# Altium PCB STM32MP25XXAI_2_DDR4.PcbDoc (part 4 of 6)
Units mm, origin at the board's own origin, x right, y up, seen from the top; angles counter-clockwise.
Board outline 172 x 137 mm, 4 copper layers (Top Layer, Signal Layer 1, Signal Layer 2, Bottom Layer), stack 1.614 mm thick; 241 components, 153 nets, 1312 pads, 924 vias.
Unrouted connection lines stored in the file: 13.
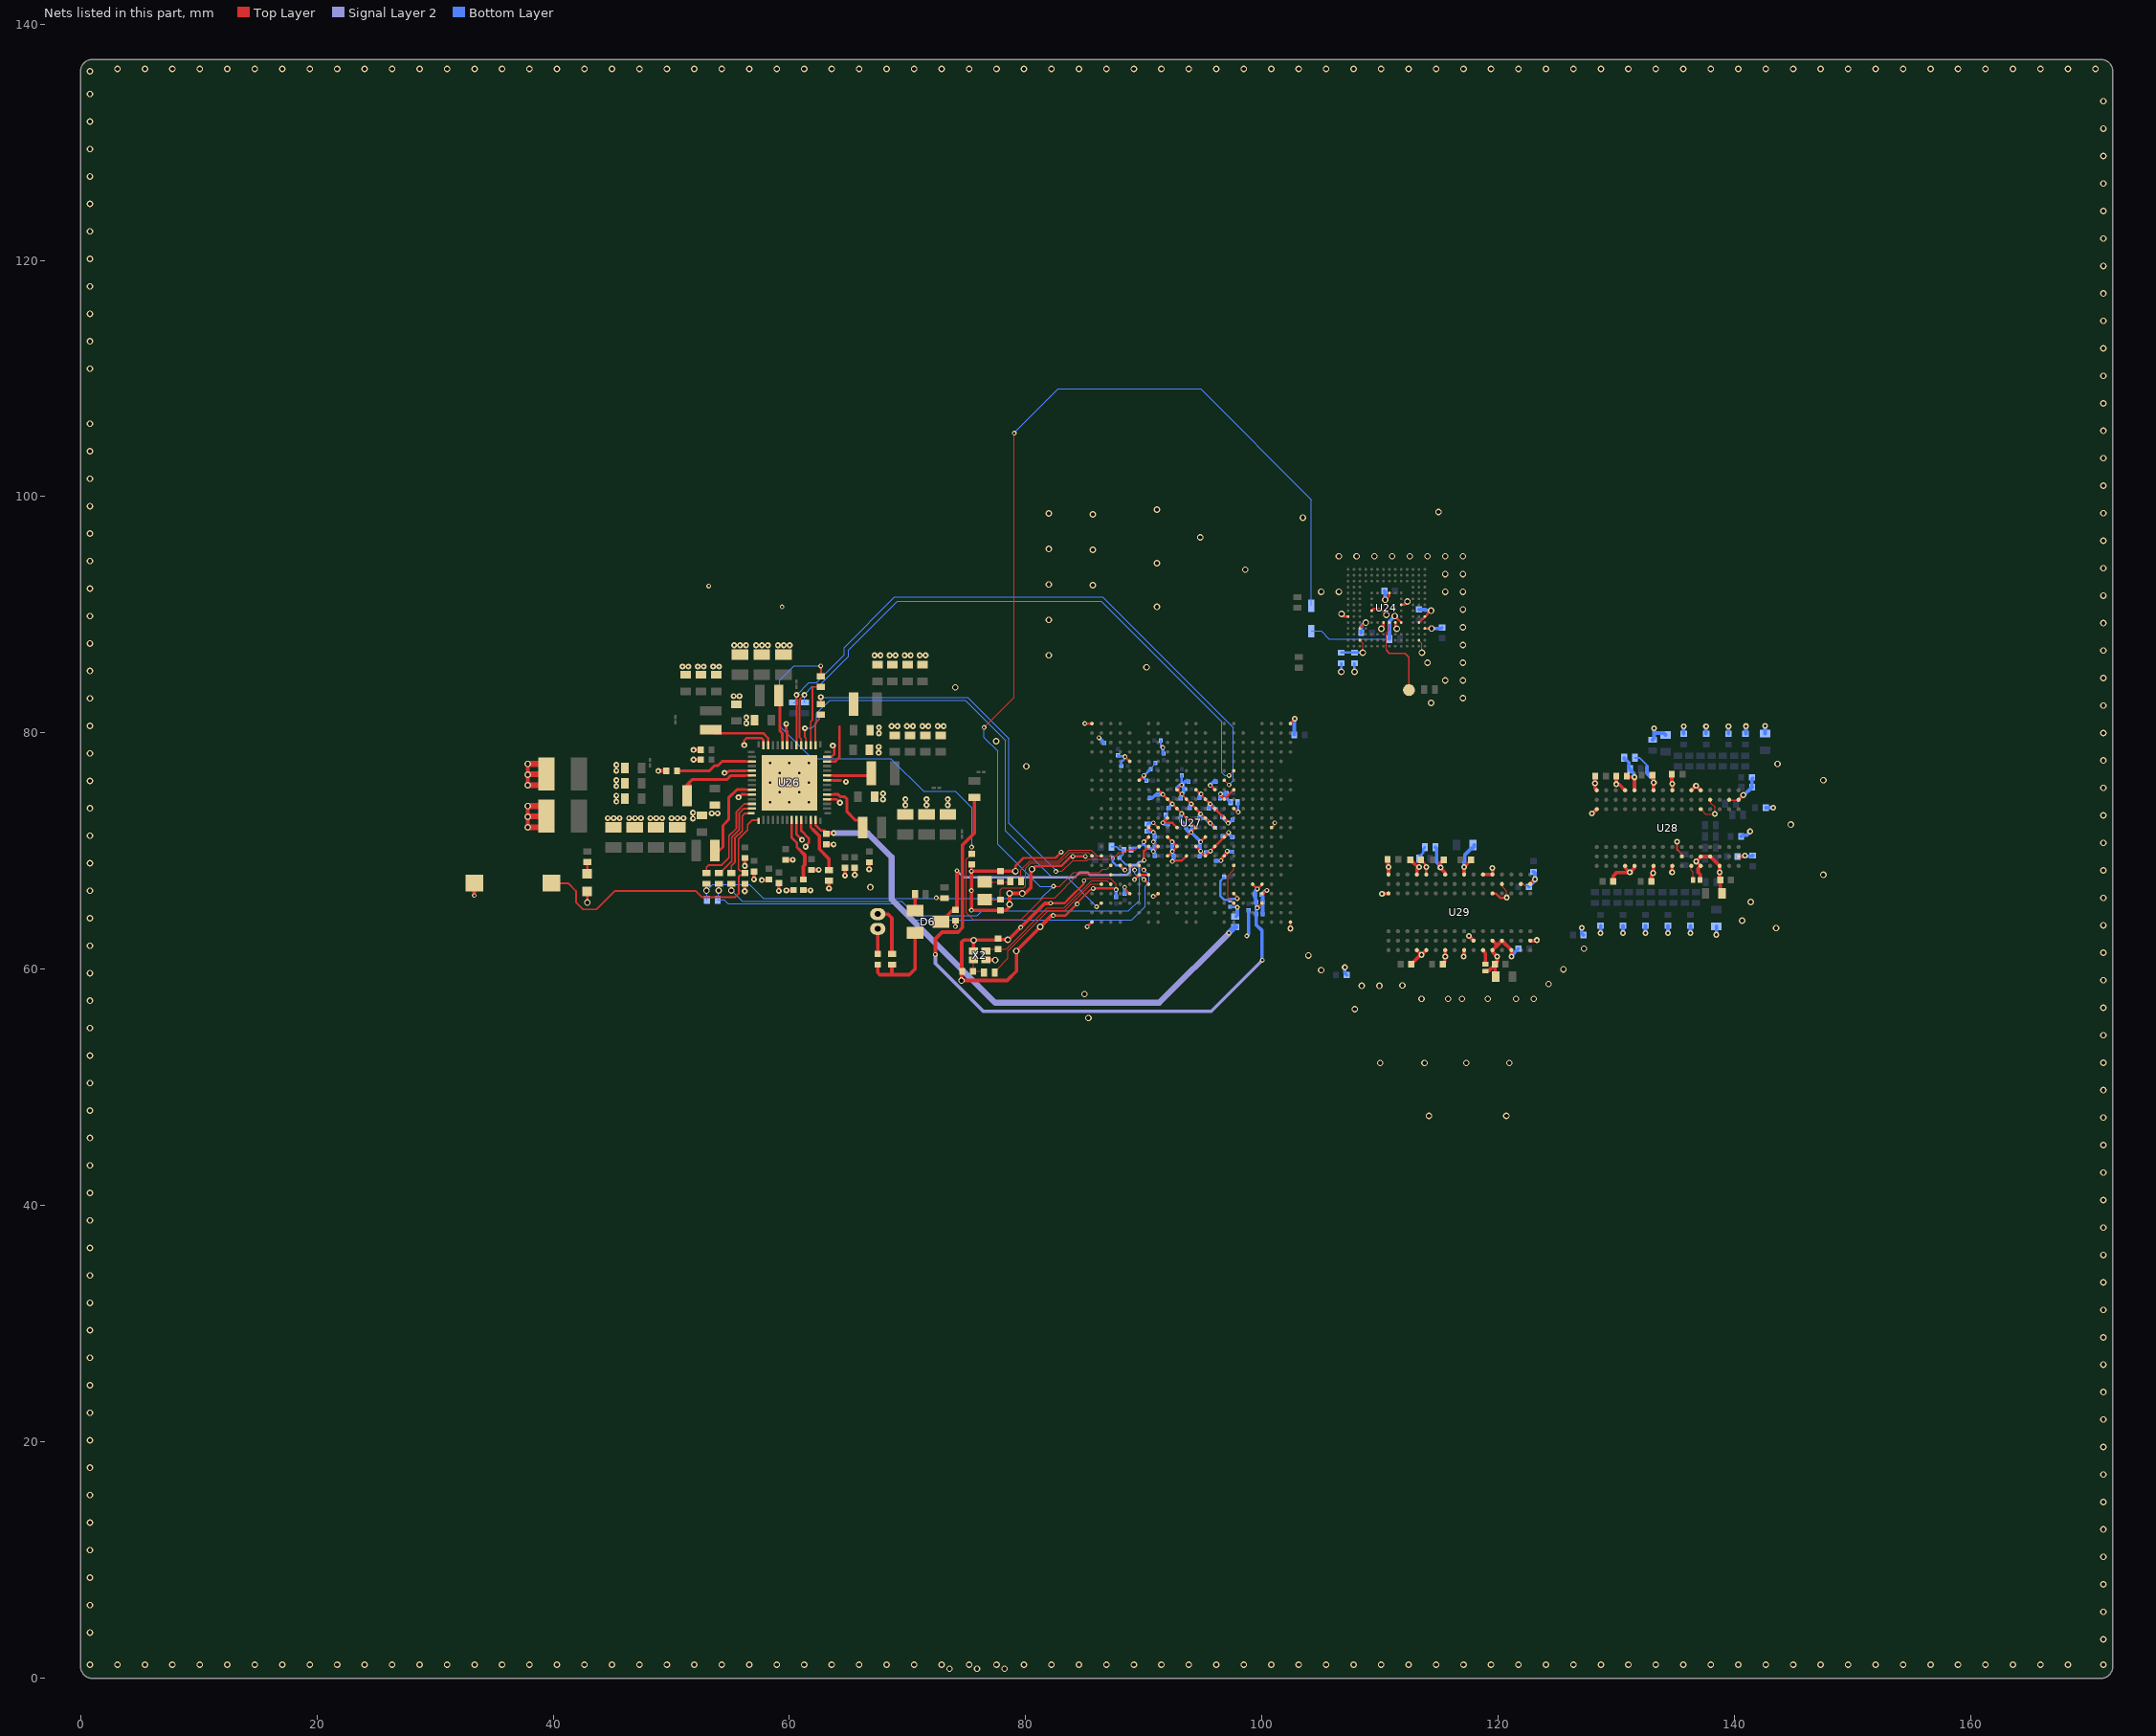
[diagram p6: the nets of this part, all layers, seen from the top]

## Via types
v1: diameter 0.55, hole 0.35, Top Layer to Bottom Layer, 432 vias
v2: diameter 0.4, hole 0.2, Top Layer to Bottom Layer, tented both sides, 202 vias
v3: diameter 0.5, hole 0.2, Top Layer to Bottom Layer, 146 vias
v4: diameter 0.5, hole 0.25, Top Layer to Bottom Layer, 144 vias

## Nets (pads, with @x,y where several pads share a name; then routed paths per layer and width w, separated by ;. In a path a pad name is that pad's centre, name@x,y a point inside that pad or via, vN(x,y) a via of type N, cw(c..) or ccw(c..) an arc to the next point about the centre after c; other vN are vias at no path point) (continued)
GND: B2.1 C1.2 C2.1 C3.1 C4.2 C5.1 C6.1 C7.1 C8.1 C9.1 C10.1 C11.2 C12.1 C13.2 C14.1 C15.1 C16.2 C17.1 C18.2 C19.1 C20.1 C21.1 C22.1 C23.1 C24.1 C25.1 C26.1 C27.1 C28.1 C29.1 C30.1 C31.1 C32.1 C33.1 C34.1 C35.1 C36.1 C37.1 C38.1 C39.1 C40.1 C41.1 C42.2 C43.1 C44.2 C45.1 C46.1 C47.2 C48.1 C49.1 C50.1 C51.1 C52.1 C53.1 C54.2 C55.1 C56.1 C57.1 C58.1 C59.1 C60.1 C61.1 C62.1 C63.1 C64.1 C65.1 C66.1 C67.1 C68.1 C69.1 C70.1 C71.1 C72.1 C73.1 C74.1 C75.1 C76.1 C77.1 C78.1 C79.1 C80.1 C81.2 C82.1 C83.1 C84.1 C85.1 C86.2 C87.1 C89.1 C90.1 C91.2 C92.2 C93.1 C94.1 C95.1 C96.1 C97.1 C98.1 C99.1 C141.2 C142.2 C152.1 C153.1 C154.1 C155.1 C156.1 C157.1 C177.1 C178.1 C179.1 C180.1 C181.1 C182.1 C183.1 C184.1 C186.1 C187.1 C188.1 C189.1 C190.2 C193.1 C199.1 C200.1 C202.1 C204.1 C206.1 C207.1 C208.2 C209.1 C211.1 C212.1 C217.2 C226.1 C234.1 C236.1 C238.1 C239.1 C245.1 C247.1 C254.1 C255.1 C256.1 C257.1 C258.1 C259.1 C261.1 C262.1 C264.1 C275.1 C276.1 C277.1 C278.1 C279.1 C280.1 C281.1 C282.1 C283.1 C284.1 C285.1 LD11.2 R57.1 R63.1 R73.1 R252.1 R262.1 R301.1 R303.1 U24.A6 U24.C4 U24.E7 U24.G5 U24.H10 U24.J5 U24.K8 U24.N2 U24.N5 U24.P4 U24.P6 U26.9 U26.10 U26.18 U26.22 U26.27 U26.36 U26.41 U26.47 U26.52 U26.57 U27.A1 U27.A22 U27.AB1 U27.AB22 U27.E5 U27.G6 U27.H8 U27.H10 U27.H12 U27.H14 U27.H16 U27.J9 U27.J11 U27.J13 U27.J15 U27.K10 U27.K12 U27.K14 U27.L9 U27.L11 U27.L13 U27.L15 U27.M7 U27.M10 U27.M12 U27.M14 U27.M20 U27.N7 U27.N9 U27.N11 U27.N13 U27.N15 U27.P8 U27.P10 U27.P12 U27.P14 U27.R9 U27.R11 U27.R13 U27.R15 U27.T4 U27.U6 U27.U7 U27.W5 U27.W8 U27.W16 U27.W19 U28.A2 U28.A8 U28.B2 U28.C9 U28.D2 U28.D8 U28.E1 U28.E3 U28.E8 U28.E9 U28.F1 U28.G8 U28.H1 U28.H9 U28.K1 U28.K9 U28.M9 U28.N1 U28.N9 U28.T1 U28.T3 U29.A2 U29.A8 U29.B2 U29.C9 U29.D2 U29.D8 U29.E1 U29.E3 U29.E8 U29.E9 U29.F1 U29.G8 U29.H1 U29.H9 U29.K1 U29.K9 U29.M9 U29.N1 U29.N9 U29.T1 U29.T3 X2.2 X2.4 | length 281.4
  Top Layer w0.09: v2(84.925,67.5) 85.12,67.695 87.155,67.695 87.183,67.667 87.65,67.2 v2(87.65,66.75) ; U24.N2@113.275,87.85 113.525,87.6 v1(113.525,86.8) ; U28.F1@136.307,75.146 U28.F1@136.326,75.127
  Top Layer w0.1: v3@44.624,72.799 v3@44.625,72.8 ; X2.2@75.547,61.575 X2.2@75.548,61.576 ; v1@75.573,62.448 v1(75.587,62.462) v1@75.6,62.475 ; v4@110.15,66.435 v4@110.155,66.43 ; v4@110.155,66.402 v4@110.155,66.43 ; v4@110.163,66.422 v4@110.155,66.43 ; U29.D2@120.3,67.225 120.343,67.183 120.343,66.972 120.7,66.615 v4(120.7,66.08) ; U29.B2@121.9,67.225 122.122,67.225 122.232,67.115 122.59,67.115 U29.A2@122.7,67.225 122.825,67.35 ; U28.E3@137.125,73.525 137.158,73.525 137.533,73.15 138.31,73.15 138.332,73.128 138.332,73.718 137.975,74.075 137.975,74.285 U28.D2@137.932,74.328
  Top Layer w0.15: v2(84.345,65.531) 84.345,65.598 84.448,65.702 84.448,65.708 85.465,66.725 85.523,66.725 85.636,66.838 v2(85.703,66.838) ; v4(135.125,70.8) 135.125,70.125 135.525,69.725 U28.G8@135.525,69.55 ; U28.B2@139.525,74.35 139.566,74.31 140.285,74.31 U28.A2@140.325,74.35
  Top Layer w0.2: v1(42.887,65.648) LD11.2@42.887,66.577 ; U26.27@63.17,78 63.579,78 63.77,78.191 63.77,78.91 v3@63.816,78.956 ; v3(63.67,78.93) v3@63.727,78.873 ; C87.1@74.05,64.125 74.05,63.634 v2(74.051,63.633) ; v2(75.402,68.305) 75.416,68.319 C33.1@75.416,68.915 ; v1(79.125,68.3) 79.125,68.75 79.8,69.425 82.507,69.425 v2(83.002,69.92) ; v1(80.525,68.475) 80.568,68.475 80.818,68.725 81.262,68.725 81.287,68.75 83.012,68.75 83.784,69.522 83.94,69.522 v2(83.978,69.56) v2(85.046,69.56) ; v2(82.1,65.6) 83.28,65.6 83.703,66.023 84.887,67.207 84.887,67.462 v2(84.925,67.5) ; v2(82.325,64.55) 83.364,64.55 v2(84.345,65.531) ; v2(85,80.805) 85.005,80.8 U27.A1@85.6,80.8 ; v2(85.2,63.6) U27.AB1@85.6,64 ; v2(85.703,66.838) 87.508,66.838 87.596,66.75 v2(87.65,66.75) ; U27.T4@88,68.8 v2(88.4,68.4) ; v2(88.37,66.944) 88.408,66.905 88.408,66.792 U27.W5@88.8,66.4 ; v2(88.4,78) U27.E5@88.8,77.6 ; v2(89.2,67.6) U27.U6@89.6,68 U27.U7@90.4,68 ; U27.G6@89.6,76 v2(90,76.4) ; v2(90,70.8) U27.N7@90.4,71.2 ; v2(90.788,66.173) 90.827,66.211 90.984,66.211 91.173,66.4 U27.W8@91.2,66.4 ; v2@90.8,70 U27.P8@91.2,70.4 v2(90.8,70.8) ; U27.H8@91.2,75.2 v2(91.6,74.8) U27.J9@92,74.4 v2(92.4,74) v2@93.225,73.175 ; U27.R9@92,69.6 92.025,69.6 v2(92.4,69.975) 92.8,70.375 U27.P10@92.8,70.4 92.4,70.8 U27.N9@92,71.2 ; U27.L9@92,72.8 v2(91.6,72.4) 92.4,72.4 U27.M10@92.8,72 ; v2@92.454,69.1 92.4,69.1 92.5,69.2 93.2,69.2 U27.R11@93.6,69.6 ; v2(93.2,73.175) v2@93.225,73.175 ; v2(93.201,75.6) 92.801,75.2 v2@93.226,74.775 ; v2(93.226,74.85) v2@93.226,74.775 ; U27.N11@93.6,71.2 v2(94,71.6) U27.M12@94.4,72 v2@93.225,73.175 ; U27.P12@94.4,70.4 v2(94.8,70) U27.R13@95.2,69.6 95.787,70.188 ; U27.H12@94.407,75.2 94.757,74.85 v2(94.832,74.85) 94.832,74.775 v2(95.607,74) U27.L15@96.807,72.8 ; v2(94.8,70.8) U27.N13@95.2,71.2 ; v2@95.625,75.575 U27.H14@96,75.2 ; U27.P14@96,70.4 95.787,70.188 ; U27.M14@96,72 95.626,72.375 94.851,73.15 v2(94.801,73.15) 94.801,73.2 v2(94.001,74) v2@93.226,74.775 ; v2(96.475,74.85) 96.514,74.812 96.514,74.686 U27.J15@96.8,74.4 U27.H16@97.6,75.2 ; U27.L15@96.8,72.8 97.087,72.513 97.087,72.413 v2(97.125,72.375) ; v2(97.175,71.575) 95.787,70.188 ; U27.W16@97.6,66.4 97.862,66.138 97.862,66.038 v2(97.9,66) ; U27.W19@100,66.4 100.019,66.419 100.144,66.419 v2(100.4,66.675) ; U27.M20@100.825,72 U27.M20@100.8,72 101.018,72.218 101.018,72.343 v2(101.075,72.4) v2@101.075,72.329 ; v4(102.4,63.45) U27.AB22@102.4,64 ; U27.A22@102.4,80.8 102.4,80.811 102.75,81.161 v4@102.75,81.175 ; v1(106.725,90.075) 106.95,89.85 U24.A6@107.275,89.85 ; U24.C4@108.275,88.85 108.725,89.3 108.735,89.3 v1(108.775,89.34) ; U24.E7@109.275,90.35 109.426,90.501 110.011,90.501 110.516,89.995 v1(110.525,89.995) ; v1(110.1,88.825) 110.1,88.913 110.275,89.088 U24.G5@110.275,89.35 ; v1(110.425,91.275) 110.775,91.625 U24.H10@110.775,91.85 ; U24.J5@111.275,89.35 111.275,89.045 111.4,88.92 v1(111.4,88.825) ; U24.K8@111.775,90.85 112.025,90.85 v1(112.3,91.125) ; U24.N5@113.275,89.35 U24.P6@113.775,89.85 114.275,90.35 v1(114.3,90.35) ; U24.P4@113.775,88.85 v1(114.35,88.85) ; U29.E3@119.5,66.425 119.503,66.422 119.769,66.422 120.142,66.05 120.67,66.05 v4(120.7,66.08) ; v4@120.687,66.012 v4@120.7,66.025
  Top Layer w0.21: v3(56.175,78.975) 56.175,79.375 56.38,79.58 57.609,79.58 57.8,79.389 U26.41@57.8,78.97 ; 56.275,74.8 U26.52@56.83,74.8 ; 56.275,76.8 U26.47@56.83,76.8 ; U26.36@59.8,78.97 59.8,79.525 ; U26.9@60.6,72.63 60.6,71.42 v3(61.068,70.952) ; U26.10@61,72.63 61,71.734 61.635,71.099 61.635,70.72 61.37,70.456 v3(61.37,70.377) ; U26.18@63.17,74.4 63.972,74.4 v3(64.272,74.1) ; U26.22@63.17,76 63.725,76
  Top Layer w0.25: v3(54.508,76.625) 54.556,76.673 54.757,76.673 54.884,76.8 56.275,76.8 ; v3(55.687,74.563) 55.721,74.563 55.959,74.8 56.275,74.8 ; v3(59.725,80.775) 59.725,80.214 59.8,80.139 59.8,79.525 ; 63.725,76 64.33,76 ; v3@64.257,74.1 v3(64.272,74.1)
  Top Layer w0.3: v2(33.319,66.245) 33.324,66.25 33.324,67.279 B2.1@33.34,67.295 ; v1(37.848,72.014) v1(37.848,72.914) v1(37.848,73.814) ; v1(37.848,75.576) v1(37.848,76.476) v1(37.848,77.376) ; v3(48.895,76.79) C43.1@49.555,76.79 ; v3(51.885,77.75) C40.1@52.495,77.75 ; v3(51.885,78.575) C39.1@52.495,78.575 ; v3@56.225,68.81 C217.2@56.225,69.42 ; v3@56.227,66.58 C155.1@56.227,67.185 ; v3(57,67.61) C154.1@57,68.215 ; v3(57.665,67.55) C142.2@58.275,67.55 ; v3@59.1,66.69 C141.2@59.1,67.3 ; C153.1@59.675,69.27 v3(60.285,69.27) ; v3(59.74,66.68) C91.2@60.35,66.68 ; C208.2@61.175,66.68 v3(61.785,66.68) ; C209.1@61.85,68.42 v3(62.485,68.42) ; C156.1@63.125,70.57 v3(63.735,70.57) ; v3(63.35,66.84) R57.1@63.35,67.5 ; v3(64.7,67.93) C189.1@64.7,68.59 ; v3(65.525,67.99) C188.1@65.525,68.59 C188.1@65.525,68.65 ; v3@66.75,68.465 66.747,68.467 66.747,69.063 C190.2@66.75,69.065 ; C92.2@74.563,59.875 74.563,59.087 74.588,59.063 78.438,59.063 79.225,59.85 79.225,61.525 v1(79.2,61.55) 81.225,63.575 v1(81.225,63.6) 82.156,64.531 82.306,64.531 v2(82.325,64.55) ; C92.2@74.625,59.825 74.576,59.874 74.576,62.299 74.752,62.475 75.6,62.475 76,62.475 76.013,62.488 76.663,62.488 76.675,62.475 77.5,62.475 77.625,62.6 C90.1@77.65,62.6 77.736,62.514 v1@78.475,62.514 ; v2(75.4,65) C86.2@77.85,65 ; 75.4,65.275 v2@75.4,66.65 ; v2@75.4,68.3 v2@75.402,68.3 ; v2(75.402,66.655) v2@75.402,68.3 ; v2(75.402,68.305) v2@75.402,68.3 ; X2.2@75.573,61.551 v1@75.573,62.448 ; X2.4@76.66,60.788 76.667,60.794 77.408,60.794 v1(77.415,60.788) ; C86.2@77.955,65.105 C86.2@77.85,65 ; v1(78.475,62.5) 78.525,62.5 v2(79.575,63.55) 81.606,65.581 v2@82.081,65.581 ; v1(79.125,68.3) C81.2@77.85,68.3 v2@75.402,68.3 ; v1(80.525,68.475) 80.43,68.38 80.43,66.905 79.993,66.468 79.748,66.468 v1(79.7,66.42) 79.695,66.425 v1(78.625,66.425) v1(78.625,65.5) 78.578,65.452 78.578,65.239 78.339,65 C86.2@77.85,65 ; U27.M7@90.4,72 v2(90.8,71.6) ; v2(96.525,69.2) 96.544,69.219 96.544,69.344 U27.R15@96.8,69.6 96.975,69.775 96.975,69.898 97.05,69.973 v2(97.05,70) ; v4@110.155,66.402 110.166,66.413 110.688,66.413 U29.T3@110.7,66.425 ; C77.1@110.625,69.3 110.663,69.263 110.663,68.688 v4(110.7,68.65) U29.T1@110.7,68.025 ; C78.1@112.55,69.275 112.55,69.25 112.655,69.145 112.68,69.145 113.143,68.682 113.198,68.682 113.236,68.644 113.236,68.59 113.136,68.49 113.136,68.452 113.1,68.416 U29.N1@113.1,68.025 ; C95.1@112.625,60.425 113.425,61.225 v4(113.5,61.225) ; U29.N9@113.1,61.625 v4(113.5,61.225) ; U29.M9@113.9,61.625 v4(113.5,61.225) ; C94.1@115.294,60.422 115.294,60.447 115.462,60.615 115.462,61.037 v4(115.5,61.075) U29.K9@115.5,61.625 ; C76.1@115.375,69.275 115.375,69.25 115.27,69.145 115.246,69.145 115.071,68.969 115.071,68.621 115.05,68.6 115.491,68.159 115.491,68.035 U29.K1@115.5,68.025 ; v4(117.05,61.075) 117.1,61.125 U29.H9@117.1,61.625 ; U29.H1@117.1,68.025 v4(117.1,68.65) ; v4(117.1,68.65) 117.57,69.12 117.57,69.17 C80.1@117.675,69.275 ; v4(117.5,62.825) U29.G8@117.9,62.425 ; U29.F1@118.7,68.025 U29.E1@119.5,68.025 v4(119.5,68.575) ; R73.1@118.9,59.85 118.95,59.9 119.208,59.9 119.595,60.287 119.595,60.295 119.709,60.409 119.717,60.409 119.717,59.458 C99.1@119.775,59.4 ; U29.E8@119.5,62.425 119.836,62.089 119.836,62.067 119.894,62.009 ; U29.E9@119.51,61.625 119.894,62.009 ; U29.E9@119.52,61.606 119.52,61.456 v4(119.9,61.075) 119.9,60.65 C93.1@119.688,60.438 ; 119.894,62.015 119.894,62.009 ; U29.D8@120.3,62.415 119.894,62.009 ; U29.D8@120.3,62.425 U29.C9@121.1,61.625 v4(121.1,61.075) ; U29.A8@122.7,62.425 v4@123.2,62.425 ; 122.825,67.35 v4(123.1,67.625) ; v4@127.855,73.231 127.935,73.231 127.942,73.238 128.014,73.238 U28.T3@128.325,73.55 ; C51.1@128.195,76.371 128.185,76.361 128.185,75.76 v4(128.175,75.75) 128.175,75.314 128.325,75.164 U28.T1@128.325,75.15 ; C83.1@129.725,67.45 129.725,67.903 130.022,68.2 v4(131.125,68.2) ; v4(129.965,75.675) 130.003,75.637 130.239,75.637 U28.N1@130.716,75.16 ; v4@129.97,75.68 129.97,76.345 C49.1@129.975,76.35 ; U28.N9@130.725,68.75 130.725,68.6 v4(131.125,68.2) ; U28.M9@131.525,68.75 131.525,68.6 v4(131.125,68.2) ; C84.1@132.95,67.45 132.95,67.893 133,67.943 133,68.05 v4(133.1,68.15) 133.125,68.175 U28.K9@133.125,68.75 ; C50.1@133.025,76.425 133.112,76.338 133.112,75.838 v4(133.15,75.8) 133.125,75.775 U28.K1@133.125,75.15 ; C48.1@134.675,76.375 134.675,75.75 v4(134.725,75.7) U28.H1@134.725,75.15 ; v4(134.7,68.2) 134.7,68.725 U28.H9@134.725,68.75 ; U28.F1@136.325,75.15 v4(136.725,75.55) U28.E1@137.132,75.143 ; R63.1@137.075,67.55 137.075,68.025 136.9,68.2 136.9,68.525 U28.E9@137.125,68.75 v4(136.75,69.125) 137.125,69.5 U28.E8@137.125,69.55 U28.D8@137.925,69.55 U28.C9@138.725,68.75 v4(138.725,68.2) 138.725,67.6 C82.1@138.775,67.55 138.793,67.533 138.793,66.558 C85.1@138.925,66.425 ; U28.A8@140.325,69.55 140.325,69.526 140.631,69.526 140.729,69.623 140.874,69.623 v4(140.875,69.625) ; U28.A2@140.325,74.35 v4(140.725,74.75)
  Top Layer w0.5: v1(37.848,72.014) 39.39,72.014 C18.2@39.437,72.061 ; v1(37.848,72.914) 37.862,72.914 37.909,72.961 C18.2@39.437,72.961 ; v1(37.848,73.814) C18.2@39.379,73.814 ; v1(37.848,75.576) 39.39,75.576 C42.2@39.437,75.623 ; v1(37.848,76.476) 37.862,76.476 37.909,76.523 C42.2@39.437,76.523 ; v1(37.848,77.376) C42.2@39.379,77.376
  Bottom Layer w0.1: C73.1@90.575,76.925 90.7,77.05 90.7,77.13 90.85,77.28 90.85,77.35 C66.1@90.9,77.4 ; C212.1@91.86,73.1 92.032,73.272 92.032,73.582 C3.1@92.1,73.65 ; C10.1@92.35,70.327 C10.1@92.35,70.45 ; 132.555,77.141 132.555,77.262
  Bottom Layer w0.15: R303.1@131.55,77.9 131.952,77.9 132.639,77.213 132.639,76.517
  Bottom Layer w0.2: C75.1@87.375,69.425 87.375,69.075 87.65,68.8 87.9,68.8 88.3,68.4 v2(88.4,68.4) ; C70.1@87.8,78.1 87.862,78.038 88.362,78.038 v2(88.4,78) 88.405,77.996 88.405,77.854 88.205,77.655 88.18,77.655 88.163,77.655 88.075,77.567 C275.1@88.075,77.2 ; C79.1@88.9,70.125 89.075,70.3 89.625,70.3 89.962,70.636 89.962,70.761 v2(90,70.8) 90.038,70.761 90.038,70.522 C234.1@90.275,70.285 ; v2@89.988,76.388 90.038,76.338 90.038,76.137 C69.1@90.205,75.97 ; v2(90,76.4) 90.525,76.925 C73.1@90.575,76.925 ; C66.1@90.9,77.4 C66.1@90.975,77.475 ; C97.1@91.425,79.375 91.425,78.955 91.6,78.781 v2(91.6,78.775) ; v2(93.201,75.6) C71.1@93.201,76.4 ; C11.2@95.25,69.9 95.312,69.962 95.587,69.962 v2(95.625,70) ; C89.1@96.75,67.8 96.75,67.75 96.45,67.45 96.45,66.225 96.775,65.9 97.3,65.9 97.35,65.95 97.444,65.95 97.456,65.962 97.721,65.962 97.862,65.962 v2(97.9,66) ; v1(106.7,85.175) C181.1@106.7,85.9 ; v1(107.825,85.175) C182.1@107.825,85.9
  Bottom Layer w0.3: v2(86.194,79.6) 86.2,79.6 C98.1@86.625,79.175 ; C67.1@87.65,66.095 v2(87.65,66.75) ; v2(88.37,66.944) 88.375,66.938 C68.1@88.375,66.4 ; C234.1@90.275,70.285 90.3,70.26 90.549,70.26 90.781,70.028 90.781,69.994 v2(90.8,69.975) ; C61.1@90.317,71.688 90.367,71.638 90.735,71.638 90.773,71.6 v2(90.8,71.6) 90.8,71.573 90.9,71.473 90.9,71.225 C52.1@90.925,71.2 90.925,70.925 v2(90.8,70.8) 90.925,70.675 C47.2@90.925,70.388 90.925,70.1 v2(90.8,69.975) ; C74.1@90.5,74.5 90.725,74.5 91.025,74.8 C6.1@91.2,74.8 v2(91.6,74.8) ; C44.2@90.925,69.6 90.925,69.85 v2(90.8,69.975) ; C72.1@91.6,78.25 v2@91.6,78.775 ; 91.86,72.925 91.86,72.687 91.6,72.427 v2(91.6,72.4) 91.725,72.275 C46.1@92.025,72.275 ; C3.1@92.1,73.65 92.1,73.7 v2(92.4,74) ; C10.1@92.35,70.327 92.381,70.296 92.381,70.021 92.4,70.002 v2(92.4,69.975) ; C10.1@92.35,70.45 92.375,70.475 92.375,70.748 92.4,70.773 v2@92.4,70.8 ; v2@92.4,69.948 92.425,69.923 92.425,69.605 C45.1@92.475,69.555 ; v2@92.525,69.216 C45.1@92.525,69.6 ; C4.2@92.825,75.25 92.825,75.4 93.025,75.6 v2(93.201,75.6) ; C5.1@93.101,74.475 93.101,74.725 93.351,74.975 93.351,75.45 v2(93.201,75.6) ; v2(93.2,73.175) 93.175,73.175 93.1,73.1 C1.2@93.1,72.825 93.1,72.55 93.225,72.425 93.304,72.425 93.45,72.279 93.45,72.2 93.575,72.075 C9.1@93.575,72 ; 93.65,71.775 93.825,71.6 v2(94,71.6) ; C17.1@93.775,75.875 93.476,75.875 v2(93.201,75.6) ; C2.1@93.876,73.65 93.876,73.875 v2(94.001,74) ; C7.1@94.125,72 94,71.875 v2(94,71.6) ; C31.1@94.675,72.775 95.201,72.775 v2(95.601,72.375) 95.625,72.375 C57.1@96.026,71.974 ; C31.1@94.676,72.825 94.676,73.075 94.751,73.15 v2(94.801,73.15) ; C14.1@94.7,74.48 94.7,74.718 v2(94.832,74.85) ; C12.1@94.75,69.575 94.8,69.625 v2(94.8,70) 94.725,70.075 94.725,70.725 v2(94.8,70.8) v2(94,71.6) ; C13.2@95.507,73.625 95.507,73.9 v2(95.607,74) ; v2@95.607,73.999 C60.1@96.081,73.524 ; v2@95.607,75.6 95.607,75.575 95.907,75.875 C16.2@96.075,75.875 ; C59.1@96.1,69.175 96.113,69.187 96.513,69.187 v2(96.525,69.2) ; C15.1@96.438,74.513 96.475,74.55 v2(96.475,74.85) 96.9,74.85 96.95,74.9 96.95,74.523 R262.1@97.324,74.149 ; C56.1@96.649,72.831 96.649,72.849 96.624,72.874 96.632,72.875 96.925,72.582 96.925,72.575 v2(97.125,72.375) 97.145,72.394 97.245,72.394 C58.1@97.5,72.65 ; C55.1@96.65,71.275 96.875,71.275 v2(97.175,71.575) 97.194,71.556 97.194,71.456 C54.2@97.475,71.175 ; v2(97.05,70) v2@97.05,70.036 ; v2@97.2,70 97.25,69.95 C53.1@97.45,69.95 ; v2(98.7,62.825) 98.7,62.835 98.85,62.985 C96.1@98.85,65 ; C63.1@100.05,64.675 C64.1@100.05,65.675 100.05,66.2 C65.1@99.925,66.325 100.256,66.656 v2@100.381,66.656 ; C276.1@102.72,79.846 102.72,81.145 v4@102.75,81.175 ; v4(107,60.175) 107,59.675 C264.1@107.15,59.525 ; C180.1@108.4,88.475 108.4,89.049 108.643,89.292 108.727,89.292 v1(108.775,89.34) ; C177.1@110.35,92.025 110.425,91.95 v1(110.425,91.275) ; C178.1@113.275,90.45 113.279,90.446 113.829,90.446 113.9,90.375 114.275,90.375 v1(114.3,90.35) ; v1(114.35,88.85) 115.15,88.85 C179.1@115.225,88.925 ; R301.1@114.675,70.325 114.767,70.233 114.767,69.065 115,68.832 115,68.779 115.1,68.679 v4(115.1,68.625) ; v4@117.097,68.575 117.097,69.058 117.15,69.111 117.15,69.668 117.712,70.23 117.78,70.23 117.95,70.4 C236.1@117.95,70.525 ; v4(121.1,61.075) 121.1,61.15 C262.1@121.7,61.75 ; C245.1@122.575,66.975 123.1,67.5 v4(123.1,67.625) 123.1,68.125 C247.1@122.975,68.25 C247.1@122.95,68.25 ; v4(127.05,63.525) 127.05,63.05 C261.1@127.2,62.9 ; v4(128.65,63.075) C259.1@128.65,63.7 ; v4(130.55,63.075) C258.1@130.55,63.7 ; v4(132.45,63.075) C257.1@132.45,63.7 ; 132.555,77.141 132.555,76.601 132.639,76.517 133.112,76.045 133.112,75.838 v4(133.15,75.8) ; R252.1@133.05,79.425 133.07,79.425 133.175,79.53 133.175,79.995 ; v4(133.175,80.4) 133.175,79.995 ; C278.1@134.15,79.825 133.98,79.995 133.175,79.995 ; v4(134.35,63.075) C256.1@134.35,63.7 ; C280.1@135.675,79.925 v4(135.675,80.55) ; v4(136.25,63.075) C255.1@136.25,63.7 ; C284.1@137.575,79.925 v4(137.575,80.55) ; v4(138.45,62.925) C254.1@138.45,63.65 ; C283.1@139.475,79.925 v4(139.475,80.55) ; C239.1@140.25,69.55 140.85,69.55 140.875,69.575 141.475,69.575 C238.1@141.525,69.625 ; C226.1@140.55,71.25 140.648,71.347 141.025,71.347 141.3,71.623 v4(141.3,71.675) ; v4(140.725,74.75) 140.764,74.788 140.839,74.788 141.345,75.295 141.37,75.295 141.475,75.4 C279.1@141.475,75.425 ; C282.1@140.925,79.925 140.95,79.95 v4(140.95,80.575) ; C279.1@141.45,75.425 141.45,76.1 C277.1@141.513,76.163 ; C281.1@142.575,79.95 v4(142.575,80.6) ; C211.1@142.625,73.675 v4(143.25,73.675)
  other v1: 73.55,0.8 75.875,0.8 78.2,0.8 0.8,1.15 3.125,1.15 5.45,1.15 7.775,1.15 10.1,1.15 12.425,1.15 14.75,1.15 17.075,1.15 19.4,1.15 21.725,1.15 24.05,1.15 26.375,1.15 28.7,1.15 31.025,1.15 33.35,1.15 35.675,1.15 38,1.15 40.325,1.15 42.65,1.15 44.975,1.15 47.3,1.15 49.625,1.15 51.95,1.15 54.275,1.15 56.6,1.15 58.925,1.15 61.25,1.15 63.575,1.15 65.9,1.15 68.225,1.15 70.55,1.15 72.875,1.15 75.2,1.15 77.525,1.15 79.85,1.15 82.175,1.15 84.5,1.15 86.825,1.15 89.15,1.15 91.475,1.15 93.8,1.15 96.125,1.15 98.45,1.15 100.775,1.15 103.1,1.15 105.425,1.15 107.75,1.15 110.075,1.15 112.4,1.15 114.725,1.15 117.05,1.15 119.375,1.15 121.7,1.15 124.025,1.15 126.35,1.15 128.675,1.15 131,1.15 133.325,1.15 135.65,1.15 137.975,1.15 140.3,1.15 142.625,1.15 144.95,1.15 147.275,1.15 149.6,1.15 151.925,1.15 154.25,1.15 156.575,1.15 158.9,1.15 161.225,1.15 163.55,1.15 165.875,1.15 168.2,1.15 171.2,1.15 171.2,3.3 0.8,3.875 171.2,5.625 0.8,6.2 171.2,7.95 0.8,8.525 171.2,10.275 0.8,10.85 171.2,12.6 0.8,13.175 171.2,14.925 0.8,15.5 171.2,17.25 0.8,17.825 171.2,19.575 0.8,20.15 171.2,21.9 0.8,22.475 171.2,24.225 0.8,24.8 171.2,26.55 0.8,27.125 171.2,28.85 0.8,29.45 171.2,31.175 0.8,31.775 171.2,33.5 0.8,34.1 171.2,35.825 0.8,36.425 171.2,38.15 0.8,38.75 171.2,40.475 0.8,41.075 171.2,42.8 0.8,43.4 171.2,45.125 0.8,45.725 171.2,47.45 114.125,47.6 120.675,47.6 0.8,48.05 171.2,49.775 0.8,50.375 110,52.075 113.75,52.075 117.275,52.075 120.925,52.075 171.2,52.1 0.8,52.7 171.2,54.425 0.8,55.025 85.3,55.875 107.85,56.625 171.2,56.75 0.8,57.35 113.5,57.5 115.75,57.5 116.925,57.5 119.1,57.5 121.5,57.5 123,57.5 84.975,57.9 108.427,58.602 109.927,58.602 111.875,58.625 124.25,58.75 74.563,59.05 171.2,59.075 0.8,59.675 105,59.925 125.5,60 103.925,61.175 171.2,61.4 127.25,61.75 0.8,62 143.5,63.5 171.2,63.725 140.625,64.125 0.8,64.325 141.35,65.7 171.2,66.05 0.8,66.65 66.85,66.945 147.5,68 171.2,68.375 0.8,68.975 171.2,70.7 0.8,71.3 144.75,72.25 171.2,73.025 0.8,73.625 171.2,75.35 0.8,75.95 147.5,76 80.05,77.175 143.625,77.375 171.2,77.675 0.8,78.275 77.495,79.305 171.2,80 0.8,80.6 171.2,82.325 114.3,82.55 0.8,82.925 117,82.95 74.035,83.865 115.5,84.45 117,84.45 171.2,84.65 0.8,85.25 90.219,85.569 114,85.95 117,85.95 81.95,86.575 171.2,86.975 117,87.45 0.8,87.575 117,88.95 171.2,89.3 81.95,89.575 0.8,89.9 117,90.45 91.1,90.675 171.2,91.625 105,91.95 106.5,91.95 115.5,91.95 117,91.95 0.8,92.225 85.675,92.5 81.95,92.575 115.5,93.45 117,93.45 98.575,93.825 171.2,93.95 91.1,94.375 0.8,94.55 106.5,94.95 108,94.95 109.5,94.95 111,94.95 112.5,94.95 114,94.95 115.5,94.95 117,94.95 85.675,95.5 81.95,95.575 171.2,96.275 94.775,96.55 0.8,96.875 103.45,98.225 85.675,98.5 81.95,98.575 171.2,98.6 114.936,98.709 91.1,98.9 0.8,99.2 171.2,100.925 0.8,101.525 171.2,103.25 0.8,103.85 171.2,105.575 0.8,106.175 171.2,107.9 171.2,110.225 0.8,110.825 171.2,112.55 0.8,113.15 171.2,114.875 0.8,115.475 171.2,117.2 0.8,117.8 171.2,119.525 0.8,120.125 171.2,121.85 0.8,122.45 171.2,124.175 0.8,124.775 171.2,126.5 0.8,127.1 171.2,128.825 0.8,129.425 171.2,131.15 0.8,131.75 171.2,133.475 0.8,134.075 0.8,136 3.125,136.2 5.45,136.2 7.775,136.2 10.1,136.2 12.425,136.2 14.75,136.2 17.075,136.2 19.4,136.2 21.725,136.2 24.05,136.2 26.375,136.2 28.7,136.2 31.025,136.2 33.35,136.2 35.675,136.2 38,136.2 40.325,136.2 42.65,136.2 44.975,136.2 47.3,136.2 49.625,136.2 51.95,136.2 54.275,136.2 56.6,136.2 58.925,136.2 61.25,136.2 63.575,136.2 65.9,136.2 68.225,136.2 70.55,136.2 72.875,136.2 75.2,136.2 77.525,136.2 79.85,136.2 82.175,136.2 84.5,136.2 86.825,136.2 89.15,136.2 91.475,136.2 93.8,136.2 96.125,136.2 98.45,136.2 100.775,136.2 103.1,136.2 105.425,136.2 107.75,136.2 110.075,136.2 112.4,136.2 114.725,136.2 117.05,136.2 119.375,136.2 121.7,136.2 124.025,136.2 126.35,136.2 128.675,136.2 131,136.2 133.325,136.2 135.65,136.2 137.975,136.2 140.3,136.2 142.625,136.2 144.95,136.2 147.275,136.2 149.6,136.2 151.925,136.2 154.25,136.2 156.575,136.2 158.9,136.2 161.225,136.2 163.55,136.2 165.875,136.2 168.2,136.2 170.525,136.2
  other v2: 92.4,69.125 92.39,70.8 95.6,75.575 59.375,90.675 53.175,92.437
  other v3: 56.222,66.61 59.1,66.64 66.745,68.46 56.225,68.76 51.825,72.75 44.624,72.798 45.125,72.798 45.626,72.798 46.424,72.798 46.925,72.798 47.426,72.798 48.224,72.798 48.725,72.798 49.226,72.798 50.024,72.798 50.525,72.798 51.026,72.798 53.424,73.202 53.925,73.202 51.825,73.25 69.804,73.9 71.604,73.9 73.404,73.9 58.35,74.15 60,74.15 61.65,74.15 45.35,74.2 67.92,74.375 69.804,74.401 71.604,74.401 73.404,74.401 45.35,74.7 67.92,74.875 59.175,74.975 60.825,74.975 45.35,75.5 58.35,75.8 60,75.8 61.65,75.8 64.78,75.875 45.35,76 59.175,76.625 60.825,76.625 45.35,76.8 45.35,77.3 58.35,77.45 60,77.45 61.65,77.45 67.55,78.325 67.55,78.825 67.575,79.975 67.575,80.475 68.65,80.575 69.15,80.575 69.95,80.575 70.45,80.575 71.25,80.575 71.75,80.575 72.55,80.575 73.05,80.575 56.35,80.823 56.35,81.323 55.275,83.123 55.776,83.123 50.95,85.623 51.451,85.623 52.25,85.623 52.751,85.623 53.55,85.623 54.051,85.623 67.2,86.575 67.7,86.575 68.475,86.575 68.975,86.575 69.75,86.575 70.25,86.575 71.025,86.575 71.525,86.575 55.324,87.425 55.825,87.425 56.326,87.425 57.174,87.425 57.675,87.425 58.176,87.425 59.024,87.425 59.525,87.425 60.026,87.425
  other v4: 123.25,62.475 110.15,66.4 113.3,68.645 138.325,73.15 127.9,73.2 102.775,81.2
HSE_IN: C90.2 U27.V3 X2.1 | length 13.2
  Top Layer w0.1: X2.1@76.623,61.551 76.772,61.7 C90.2@77.65,61.7 78.35,61.7 81.825,65.175 83.225,65.175 85.56,67.51 86.89,67.51 U27.V3@87.2,67.2
HSE_OUT: R75.2 U27.V2 | length 12.5
  Top Layer w0.1: R75.2@77.375,59.725 77.58,59.93 77.58,60.027 78.482,60.929 78.482,61.532 81.925,64.975 83.275,64.975 83.285,64.985 83.304,64.985 85.519,67.2 U27.V2@86.4,67.2
I2C7.SCL: R261.1 U26.33 U27.F16 | length 53.8
  Top Layer w0.09: v2@97.2,76.4 U27.F16@97.6,76.8
  Top Layer w0.15: U26.33@61,78.97 61,79.5 60.85,79.65 60.85,82.813 v3(61.262,83.225)
  Bottom Layer w0.1: v3@61.268,83.22 61.268,82.625 R261.1@61.305,82.588 ; v3@61.268,83.23 61.268,83.265 61.932,83.929 62.442,83.929 65.019,86.505 65.019,87.016 69.143,91.14 86.368,91.14 96.58,80.928 96.58,76.658 96.836,76.402 v2@97.197,76.402
  other v2: 97.2,76.4
I2C7.SDA: R260.1 U26.34 U27.G15 | length 56
  Top Layer w0.09: U27.G15@96.8,76 v2(97.2,75.6)
  Top Layer w0.15: U26.34@60.6,78.97 v3(60.6,83.225)
  Bottom Layer w0.1: R260.1@60.33,82.58 60.42,82.58 60.6,82.76 v3(60.6,83.225) ; v3@60.613,83.225 61.661,84.272 62.291,84.272 64.619,86.6 64.619,87.231 68.901,91.513 86.522,91.513 97.557,80.478 97.557,75.956 v2(97.2,75.6)
MP257_WAKEUP: U26.32 U27.Y2 | length 39.9
  Top Layer w0.09: v2(85.99,65.295) 86.042,65.295 86.348,65.6 U27.Y2@86.4,65.6
  Top Layer w0.15: v3(61.3,80.4) 61.3,79.653 61.4,79.553 U26.32@61.4,78.97
  Bottom Layer w0.1: v3(61.3,80.4) 61.881,80.4 62.3,80.819 62.3,81.657 63.418,82.775 74.895,82.775 78.295,79.375 78.295,71.723 82.182,67.835 83.45,67.835 v2(85.99,65.295)
NetB2_2: B2.2 C155.2 U26.1 | length 26.2
  Top Layer w0.15: B2.2@39.882,67.292 41.271,67.292 41.933,66.63 41.933,65.666 42.532,65.067 43.658,65.067 45.208,66.618 52.086,66.618 52.59,66.114 55.417,66.114 55.696,66.393 55.696,67.818 ; 55.7,67.825 55.847,67.972 56.054,67.972 C155.2@56.227,68.145 56.062,68.31 55.838,68.31 55.687,68.46 55.687,71.008 56.462,71.783 56.462,72.237 56.855,72.63 U26.1@57.4,72.63
NetC43_2: C43.2 U26.45 | length 6.7
  Top Layer w0.21: 56.275,77.6 U26.45@56.83,77.6
  Top Layer w0.25: C43.2@50.515,76.79 53.231,76.79 53.676,77.235 53.951,77.235 54.316,77.6 56.275,77.6
NetC49_2: C49.2 R302.1 R303.2 U28.M1 | length 3.9
  Top Layer w0.3: C49.2@130.875,76.35 130.935,76.29 131.482,76.29 v4(131.52,76.252) 131.52,75.155 U28.M1@131.525,75.15
  Bottom Layer w0.3: R303.2@130.65,77.9 130.65,77.805 130.755,77.7 130.85,77.7 131.045,77.505 131.045,77.055 R302.1@131.15,76.95 131.15,76.855 131.255,76.75 131.276,76.75 131.482,76.545 131.482,76.29 v4(131.52,76.252)
NetC61_2: C61.2 U27.M8 | length 1.1
  Top Layer w0.2: v2(90.8,72.4) U27.M8@91.2,72
  Bottom Layer w0.2: C61.2@90.317,72.288 90.391,72.362 90.762,72.362 v2(90.8,72.4)
NetC62_2: C62.2 R286.2 U27.T16 U27.Y16 | length 5.5
  Top Layer w0.1: U27.T16@97.6,68.8 97.6,68.425 97.1,67.925 97.1,66.1 U27.Y16@97.6,65.6 97.6,65.575 97.906,65.269 v2(97.906,65.243)
  Bottom Layer w0.2: C62.2@97.3,65.3 97.329,65.272 97.878,65.272 v2(97.906,65.243)
  Bottom Layer w0.3: R286.2@97.795,64.475 97.9,64.58 v2@97.9,65.238
NetC63_2: C63.2 C64.2 C65.2 R249.2 U27.V18 U27.V19 U27.Y19 | length 55.5
  Top Layer w0.2: U27.V18@99.2,67.2 v2(99.6,66.8) ; v2(99.6,65.2) U27.Y19@100,65.6 ; v2(99.6,66.8) U27.V19@100,67.2
  Top Layer w0.3: v2(72.351,61.252) 72.351,62.576 72.925,63.15 74.272,63.15 74.647,63.525 74.647,70.522 75.65,71.525 R249.2@75.65,74.55
  Signal Layer 2 w0.3: v2(72.351,61.252) 72.351,60.497 76.398,56.449 95.699,56.449 v2(100.025,60.775)
  Bottom Layer w0.3: v2(99.6,66.8) 99.397,66.597 99.397,66.347 C65.2@99.375,66.325 99.4,66.3 99.4,66.05 99.475,65.975 99.475,65.7 C64.2@99.5,65.675 99.5,65.326 99.6,65.227 v2(99.6,65.2) 99.6,65.173 99.5,65.073 C63.2@99.5,64.675 99.5,63.761 100.003,63.259 100.003,60.797 v2(100.025,60.775)
NetC75_2: C75.2 C79.2 R267.1 U27.V7 | length 5.7
  Top Layer w0.2: v2(90,67.6) U27.V7@90.4,67.2
  Bottom Layer w0.15: R267.1@87.25,70.375 87.675,70.375 87.925,70.125 C79.2@88.238,70.125 ; C79.2@88.3,70.125 88.238,70.063 88.238,69.738 C75.2@87.925,69.425 88.5,68.85 89.317,68.85 89.602,68.565 89.602,68.038 90,67.641 v2(90,67.6)
NetC78_2: C78.2 R300.1 R301.2 U29.M1 | length 3.4
  Top Layer w0.2: C78.2@113.45,69.25 113.605,69.095 113.605,69.07 113.798,68.878 113.798,68.704 v4@113.853,68.649 ; v4@113.853,68.654 113.877,68.631 113.877,68.049 U29.M1@113.9,68.025
  Bottom Layer w0.2: R300.1@113.301,69.63 113.396,69.63 113.62,69.854 113.62,70.17 R301.2@113.775,70.325 ; R300.1@113.325,69.367 113.325,69.28 113.48,69.125 113.567,69.125 113.843,68.849 113.843,68.702 v4(113.9,68.645)
NetC81_1: C81.1 R64.2 X1.1 | length 2.2
  Top Layer w0.1: X1.1@76.525,67.4 78.65,67.4 R64.2@78.7,67.45
NetC88_1: C88.1 CN12.2 | length 2.1
  Top Layer w0.3: C88.1@67.475,61.3 CN12.2@67.475,63.425
NetC88_2: C88.2 D6.2 R66.2 | length 8
  Top Layer w0.3: C88.2@67.475,60.4 67.475,59.726 67.651,59.55 68.675,59.55 ; R66.2@68.675,60.395 68.675,59.55 ; D6.2@70.625,63.075 70.625,60.025 70.15,59.55 68.675,59.55
NetC92_1: C92.1 R75.1 X2.3 | length 1.9
  Top Layer w0.09: X2.3@75.573,60.801 75.573,59.877 75.548,59.852 75.55,59.85 76.35,59.85 R75.1@76.475,59.725
NetC181_2: C181.2 C182.2 U24.C2 | length 3
  Top Layer w0.09: U24.C2@108.275,87.85 108.525,87.6 v1(108.525,86.8)
  Bottom Layer w0.2: C181.2@106.7,86.8 C182.2@107.825,86.8 v1(108.525,86.8)
NetC208_1: C208.1 U26.8 | length 5.4
  Top Layer w0.21: U26.8@60.2,72.63 60.2,71.134 60.625,70.709 60.625,70.345 60.798,70.173
  Top Layer w0.3: 60.798,70.173 61.3,69.67 61.3,68.843 61.175,68.718 C208.1@61.175,67.705
NetCN12_1: CN12.1 R66.1 | length 4.4
  Top Layer w0.3: CN12.1@67.475,64.675 68.344,64.675 68.675,64.344 R66.1@68.675,61.295
NetD5_1: D5.1 R248.1 U24.K5 | length 9.8
  Top Layer w0.2: v1(111.225,89.9) U24.K5@111.775,89.35
  Bottom Layer w0.1: D5.1@104.175,88.63 104.995,88.63 105.675,87.95 R248.1@110.775,87.95
  Bottom Layer w0.3: R248.1@110.775,87.95 110.775,89.45 v1(111.225,89.9)
NetD6_1: D6.1 R67.1 | length 1.4
  Top Layer w0.3: D6.1@70.625,64.975 R67.1@70.625,66.375
NetL1_1: L1.1 U26.37 | length 4.2
  Top Layer w0.21: U26.37@59.4,78.97 59.4,79.525
  Top Layer w0.25: L1.1@59.2,83.135 59.2,80.173 59.4,79.973 59.4,79.525
NetL2_1: L2.1 U26.26 | length 4.1
  Top Layer w0.2: U26.26@63.417,77.6 63.9,77.6 64.225,77.925 64.225,80.56 ; L2.1@65.35,81.685 L2.1@65.35,82.2
NetL3_1: L3.1 U26.40 | length 5.9
  Top Layer w0.15: L3.1@53.198,80.162 L3.1@53.35,80.01
  Top Layer w0.21: L3.1@53.35,80.275 53.635,79.99 55.41,79.99 57.765,79.99 58.2,79.555 U26.40@58.2,78.97
NetL4_1: L4.1 U26.23 | length 3.8
  Top Layer w0.15: L4.1@66.86,75.885 L4.1@66.86,76.4
  Top Layer w0.21: U26.23@63.17,76.4 63.725,76.4
  Top Layer w0.25: 63.725,76.4 66.5,76.4
NetL5_1: L5.1 U26.48 | length 7.2
  Top Layer w0.15: L5.1@51.118,74.448 L5.1@51.37,74.7 ; L5.1@51.59,74.585 L5.1@51.59,75.1
  Top Layer w0.21: 56.275,76.4 U26.48@56.83,76.4
  Top Layer w0.25: 51.325,75.6 51.775,76.05 54.7,76.05 55.05,76.4 56.275,76.4 ; L5.1@51.59,75.1 51.59,75.615
NetL6_1: L6.1 U26.19 | length 4.9
  Top Layer w0.21: U26.19@63.17,74.8 63.725,74.8
  Top Layer w0.25: 63.725,74.8 64.123,74.8 64.298,74.625 64.65,74.625 64.875,74.4 64.875,73.325 65.571,72.629 65.925,72.629 65.93,72.624 L6.1@65.93,72.025
NetL7_1: L7.1 U26.51 | length 7.4
  Top Layer w0.21: 56.275,75.2 U26.51@56.83,75.2
  Top Layer w0.25: L7.1@53.925,70.425 L7.1@53.925,70.669 ; L7.1@53.975,69.95 54.375,70.35 54.375,72.184 54.85,72.659 54.85,74.503 55.547,75.2 56.275,75.2
NetLD11_1: LD11.1 R210.2 | length 1
  Top Layer w0.2: LD11.1@42.887,68.077 R210.2@42.887,69.07
NetR2_2: R2.2 U26.56 | length 6.1
  Top Layer w0.15: R2.2@55.08,68.145 55.08,68.76 55.375,69.055 55.375,71.091 56.012,71.728 56.012,72.985 56.227,73.2 U26.56@56.755,73.2
NetR46_2: R46.2 U26.30 | length 2.8
  Top Layer w0.15: U26.30@62.2,78.97 62.2,80.87 62.532,81.202 62.532,81.43 R46.2@62.65,81.548
NetR57_2: R57.2 U26.12 | length 4.9
  Top Layer w0.21: U26.12@61.8,72.63 61.8,72.016 61.97,71.845
  Top Layer w0.3: 61.97,71.845 62.525,71.291 62.525,70.174 63.35,69.349 R57.2@63.35,68.4
NetR59_2: R59.2 U26.54 | length 8.5
  Top Layer w0.15: R59.2@52.98,68.145 52.98,68.64 53.15,68.81 54.236,68.81 54.875,69.449 54.875,71.298 55.512,71.935 55.512,73.335 56.177,74 U26.54@56.83,74
NetR60_2: R60.2 U26.55 | length 7.1
  Top Layer w0.15: R60.2@54.03,68.145 54.104,68.145 55.125,69.166 55.125,71.194 55.762,71.832 55.762,73.232 56.131,73.6 U26.55@56.83,73.6
NetR63_2: R63.2 U28.F9 | length 1.3
  Top Layer w0.09: U28.F9@136.325,68.75 136.325,68.4 136.475,68.25 R63.2@136.475,67.55
NetR73_2: R73.2 U29.F9 | length 1.3
  Top Layer w0.3: U29.F9@118.7,61.625 118.753,61.572 118.753,61.504 118.9,61.358 R73.2@118.9,60.45
NetR81_2: R81.2 U26.31 | length 5.7
  Top Layer w0.15: U26.31@61.8,78.97 61.8,80.973 61.95,81.123 61.95,83.81 62.038,83.898 R81.2@62.663,83.898
NetR262_2: R262.2 U27.K16 | length 1.4
  Top Layer w0.09: U27.K16@97.6,73.6 U27.K16@97.657,73.6
  Top Layer w0.2: U27.K16@97.657,73.6 v2@97.966,73.291
  Bottom Layer w0.09: R262.2@97.924,74.149 R262.2@97.978,74.096
  Bottom Layer w0.2: v2(97.975,73.3) R262.2@97.978,74.096
NetTP9_1: TP9.1 U24.H5 | length 7.4
  Top Layer w0.09: 110.525,87 110.525,88.468 110.775,88.718 U24.H5@110.775,89.35
  Top Layer w0.11: 110.525,87 110.775,86.75 112.106,86.75 112.43,86.426 TP9.1@112.43,83.629
NRST: C33.2 R81.1 U27.U3 | length 51
  Top Layer w0.09: 82.437,66.05 84.398,68.011 87.189,68.011 U27.U3@87.2,68
  Top Layer w0.1: v2@75.425,70.347 C33.2@75.425,69.775 75.4,69.775 75.195,69.57 75.195,69.544 74.971,69.32 74.971,64.793 75.534,64.23 79.62,64.23 81.44,66.05 82.437,66.05
  Top Layer w0.15: v2(62.651,85.672) 62.663,85.661 R81.1@62.663,84.798
  Bottom Layer w0.1: v2(62.651,85.672) 62.644,85.679 60.373,85.679 59.159,84.466 59.159,80.601 61.914,77.847 68.567,77.847 71.354,75.06 74.014,75.06 75.433,73.641 75.433,70.356 v2(75.424,70.347)
NRSTC1MS: D5.2 R27.1 R59.1 R272.1 U27.T3 | length 120.3
  Top Layer w0.09: v2(82.345,67.035) 82.859,67.035 84.03,68.206 86.216,68.206 86.49,68.48 86.88,68.48 U27.T3@87.2,68.8
  Top Layer w0.1: R59.1@52.98,67.245 52.988,67.237 v1@52.988,66.633 ; v2(72.425,66.05) 72.45,66.025 R27.1@73.125,66.025 ; v2(76.475,80.475) 79.028,83.028 v2@79.028,105.328
  Bottom Layer w0.1: R272.1@53.025,65.879 53.025,66.621 v1(52.983,66.663) 53.492,67.172 56.612,67.172 57.799,65.986 72.361,65.986 v2(72.425,66.05) 72.489,65.986 81.296,65.986 v2(82.345,67.035) 81.19,67.035 77.64,70.585 77.64,78.455 76.475,79.62 v2(76.475,80.475) ; v2@79.024,105.399 82.75,109.125 94.793,109.125 104.175,99.743 D5.2@104.175,90.77
  other v2: 79.033,105.377
OSC32_IN: C86.1 U27.R1 X1.2 | length 12.2
  Top Layer w0.09: C86.1@77.85,65.9 77.85,66.725 78,66.875 79.835,66.875 80,67.04 80,68.544 80.444,68.988 82.817,68.988 83.735,69.905 85.295,69.905 U27.R1@85.6,69.6
  Top Layer w0.1: X1.2@76.525,65.9 C86.1@77.85,65.9
OSC32_OUT: R64.1 U27.R2 | length 8.7
  Top Layer w0.09: R64.1@79.6,67.45 79.6,68.413 80.365,69.178 81.172,69.178 ; 81.172,69.175 82.75,69.175 83.66,70.085 85.532,70.085 86.017,69.6 U27.R2@86.4,69.6
PMIC_WAKEUPn: R46.1 U27.P6 | length 38.7
  Top Layer w0.09: v2(82.54,68.284) 82.555,68.298 83.068,68.298 83.983,69.212 85.187,69.212 85.289,69.315 87.318,69.315 87.332,69.315 87.495,69.478 87.495,69.492 87.705,69.702 87.705,69.722 87.878,69.895 87.898,69.895 87.899,69.896 87.899,69.9 88.371,69.9 88.546,70.075 89.275,70.075 U27.P6@89.6,70.4
  Top Layer w0.15: R46.1@62.65,82.448 v3(62.65,83.033)
  Bottom Layer w0.1: v3@62.703,83.022 75.078,83.022 78.559,79.541 78.559,72.368 82.444,68.482 82.444,68.461 82.54,68.365 v2(82.54,68.284)
PWR_CPU_ON: R60.1 R272.2 U27.T6 | length 42.5
  Top Layer w0.1: v1@54.014,66.64 54.014,67.229 R60.1@54.03,67.245 ; U27.T6@89.6,68.8 v2(90,68.4)
  Bottom Layer w0.1: R272.2@53.925,65.879 54.456,65.879 54.785,65.55 68.85,65.55 70.209,64.191 88.964,64.191 90.107,65.334 90.107,67.029 90.425,67.348 90.425,67.975 v2(90,68.4) ; R272.2@53.991,66.065 53.991,66.652 v1(54.009,66.67)
PWR_ON: R2.1 U27.T5 | length 39.8
  Top Layer w0.1: v1@55.08,66.64 R2.1@55.08,67.245 ; U27.T5@88.8,68.8 v2(89.2,68.4)
  Bottom Layer w0.1: v1(55.075,66.67) 55.119,66.67 56.017,65.772 69.502,65.772 70.717,64.558 75.903,64.558 76.287,64.942 88.706,64.942 89.615,65.85 89.615,67.702 89.206,68.111 89.206,68.394 v2(89.2,68.4)
VBAT: C87.2 D6.3 U27.P7 | length 24
  Top Layer w0.2: v2(90.019,69.225) 90.025,69.231 90.025,69.25 90.006,69.269 90.006,70.006 U27.P7@90.4,70.4
  Top Layer w0.3: D6.3@73.2,64.375 72.85,64.025 D6.3@72.825,64.025 73.188,64.388 73.825,65.025 C87.2@74.05,65.025 ; C87.2@73.925,65.125 74.17,65.125 74.175,65.13 v2(74.175,68.35)
  Signal Layer 2 w0.2: v2(74.175,68.35) 74.175,68.325 74.718,67.782 84.157,67.782 84.575,68.2 85.215,68.2 85.426,67.989 88.555,67.989 88.8,68.234 88.8,68.566 89.035,68.8 89.296,68.8 89.596,69.1 89.84,69.1 89.965,69.225 v2(90.019,69.225)
VDD3V3_USB: C156.2 R286.1 U26.13 | length 47
  Top Layer w0.21: U26.13@62.2,72.63 62.2,72.2 62.663,71.737 62.918,71.737 62.92,71.735 62.99,71.735 63.125,71.6 C156.2@63.125,71.53
  Top Layer w0.3: C156.2@63.125,71.53 v3(63.735,71.53)
  Signal Layer 2 w0.5: v3(63.735,71.53) 66.62,71.53 68.65,69.5 68.65,65.93 77.411,57.17 91.295,57.17 97.19,63.065 v2(97.19,63.078)
  Bottom Layer w0.5: v2(97.19,63.078) 97.687,63.575 R286.1@97.725,63.575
